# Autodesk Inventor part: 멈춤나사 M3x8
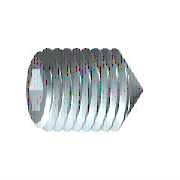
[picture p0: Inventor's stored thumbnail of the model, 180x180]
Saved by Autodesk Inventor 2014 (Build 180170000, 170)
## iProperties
IsCustomPart: 1
Created: 2012-02
Part Number: 멈춤나사 M3x8
Material: 강철, 연강
Description: 6각 소켓 머리 없는 멈춤 나사
Document SubType Name: Modeling
Standard: KS B 1028
Designer: test
Standards Organization: KS
Language: ko-KR
Size Designation: 원추점 M3x8
Categories: <MemberInstance><Categories><Category DisplayName="조임쇠" InternalName="e4da775c-781d-43d5-af7c-5136215cf5a6" Mnemonic="FSTN"><Category DisplayName="볼트" InternalN
Density: 1 g/cm^3
Appearance: 강철
Author: test
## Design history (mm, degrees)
sketch "스케치1"
  geometry: L1 (0, 0)-(5.5, 0); L2 (8, 0.866)-(8, 1.5); L3 (8, 1.5)-(0, 1.5); L4 (8, 0.866)-(6, 0.866); L5 (6, 0.866)-(5.5, 0); L6 (0, -0.3)-(0, 1.8) reference; L7 (0, 1.5)-(0, 0)
  constraints: 13 end point, 3 parallel, 1 collinear, 1 perpendicular, 1 point on line
  dimensions: "d0" = 2 distance of L2.start L4.end (= INTI); "d1" = 60 deg angle of L5 L1; "d2" = 3 diameter of L3 L1 (= NND); "d3" = 1.73205 diameter of L4 L1 (= 1.1547 x SW); "d5" = 8 distance from line of L2 L3.end (= NLG)
revolve "본체" sketch "스케치1" stored, may be unused: angle "d6" = 90 deg
sketch "스케치2"
  geometry: L1 (-0.433, 0.75)-(0.433, 0.75); L2 (0.433, 0.75)-(0.866, 0); L3 (0.866, 0)-(0.433, -0.75); L4 (0.433, -0.75)-(-0.433, -0.75); L5 (-0.433, -0.75)-(-0.866, 0); L6 (-0.866, 0)-(-0.433, 0.75); 3 further points
  constraints: 12 end point, 1 coincident, 1 horizontal, 13 other
extrude "슬롯" join sketch "스케치2" taper "d7" = 0 deg; stored distance "d21" = 10
workaxis "Work Axis1"
workplane "Work Plane1"
sketch "스케치4"
  geometry: L1 (0, 0.15)-(-1.35, 1.5) reference; L2 (0, -0.15)-(-1.35, -1.5) reference; L3 (-1.35, -1.5)-(0.15, 0); L4 (-1.35, 1.5)-(0.15, 0); 2 further points
  constraints: 4 end point, 1 coincident, 1 collinear, 1 horizontal alignment
node "작업점1"
body "Solid1"
feature "스레드" dims "d12" = 8 (= NLG), "d13" = 0
chamfer "모따기1" distance "d8" = 1.35 (computed from NND, SPD, FAWI); stored, may be unused: angle "d9" = 45 deg (= FAWI), second distance "d34" = 1.35 (computed from NND, SPD, FAWI)
chamfer "모따기2" distance "d10" = 0.30673 (= -0.5 x GD1 + 0.5 x NND); stored, may be unused: angle "d11" = 45 deg (= FAWI), second distance "d35" = 0.30673 (= -0.5 x GD1 + 0.5 x NND)
other parameters: "NND" = 3 [user parameter; used in 5 equation terms], "NLG" = 8 [user parameter; used in 2 equation terms], "INTI" = 2 [user parameter; used in 1 equation term], "FAWI" = 45 deg [user parameter; used in 4 equation terms], "SW" = 1.5 [user parameter; used in 2 equation terms], "GD1" = 2.38655 (= THREADDIA - 1.2269 x PTC) [user parameter; used in 2 equation terms], "d4" = 0, "FAWI1" = 45 deg [user parameter], "SPD" = 0.3 [user parameter; used in 2 equation terms], "d36" = 0, "d37" = 0, "GUL" = 0.30673 (= 0.61345 x PTC) [user parameter], "TOA" = 30 deg [user parameter], "THREADDIA" = 3 [user parameter; used in 1 equation term], "PTC" = 0.5 [user parameter; used in 4 equation terms], "GAL" = 0.30673 (= 0.61345 x PTC) [user parameter], "E0" = 1.7325 (= 1.155 x SW) [user parameter]
